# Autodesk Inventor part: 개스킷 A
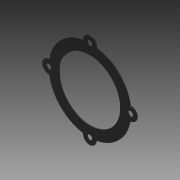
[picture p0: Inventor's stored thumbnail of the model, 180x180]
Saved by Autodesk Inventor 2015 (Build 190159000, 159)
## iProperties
Created: 2020-03
Part Number: 개스킷 A
Material: 고무
Document SubType Name: Modeling
Designer: mduedu
Density: 0.93 g/cm^3
Mass: 2.68337 g
Surface Area: 63.575 cm^2
Volume: 2.88534 cm^3
Appearance: 고무 - 검은색 - 버전 1.1
Author: mduedu
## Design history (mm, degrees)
sketch "스케치1" dims "d1" = 88
  geometry: C1 r 33 at (0, 0); C2 r 7 at (0, 44); C3 r 7 at (-38.105, -22); C4 r 7 at (38.105, -22); 2 further points
  constraints: 4 centre point, 2 coincident, 2 vertical alignment, 9 other
  dimensions: "d0" = 66 diameter of C1; "d2" = 14 diameter of C2; "d5" = 360 deg dimension on point (0, 0) C2.centre (derived)
extrude "돌출1" new body sketch "스케치1" distance "d7" = 1; taper "d8" = 0 deg
extrude "돌출2" join sketch "스케치1" stored distance "d17" = 10; taper "d18" = 0 deg
fillet "모깎기1" dims "d9" = 1
sketch "스케치2"
  geometry: C1 r 33 at (0, 0) reference; A1 r 44 centre (0, 0) between (-7.817, 43.3) and (7.817, 43.3) reference; A2 r 7 centre (0, 44) between (6.996, 44.249) and (-6.996, 44.249) reference; A3 r 1 centre (7.995, 44.284) between (6.996, 44.249) and (7.817, 43.3) reference; A4 r 1 centre (-7.995, 44.284) between (-7.817, 43.3) and (-6.996, 44.249) reference; 4 further points
hole "구멍1" sketch "스케치2" diameter "d10" = 5.5; stored, may be unused: countersink angle "d14" = 90 deg, drill point angle "d16" = 118 deg; dims "d11" = 6, "d12" = 10, "d13" = 5.7, "d15" = 8
node "솔리드1"
pattern_circular "원형 패턴1" dims "d20" = 360 deg
node "투영된 루프1"
